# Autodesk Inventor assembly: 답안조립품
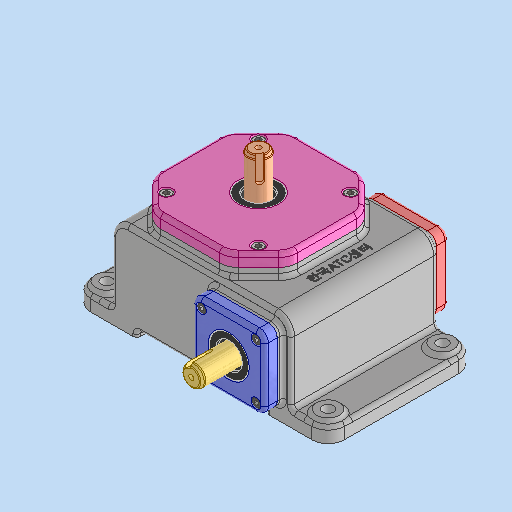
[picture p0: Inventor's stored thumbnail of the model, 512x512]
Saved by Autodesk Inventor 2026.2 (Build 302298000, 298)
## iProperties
Created: 2026-02
Part Number: 답안조립품
Document SubType Name: Assembly
Designer: PC2-07
Author: PC2-07
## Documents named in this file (15)
- C:\Users\PC2-07\Desktop\760203V1008\답안조립품.iam
- C:\Users\PC2-07\Desktop\760203V1008\본체.ipt
- C:\Users\PC2-07\Desktop\760203V1008\웜 샤프트.ipt
- C:\Users\PC2-07\Desktop\760203V1008\뒷커버.ipt
- C:\Users\PC2-07\Desktop\760203V1008\앞커버.ipt
- C:\Users\PC2-07\Desktop\760203V1008\테이퍼 롤러 베어링 30203.ipt
- C:\Users\PC2-07\Desktop\760203V1008\오일 실 17 32 8.ipt
- C:\Users\PC2-07\Desktop\760203V1008\웜 휠 커버.ipt
- C:\Users\PC2-07\Desktop\760203V1008\축.ipt
- C:\Users\PC2-07\Desktop\760203V1008\평행 키 5x5x16.ipt
- C:\Users\PC2-07\Desktop\760203V1008\웜 휠.ipt
- C:\Users\PC2-07\Desktop\760203V1008\칼라.ipt
- C:\Users\PC2-07\Desktop\760203V1008\6각 구멍붙이 볼트 M5x10.ipt
- C:\Users\PC2-07\Desktop\760203V1008\6각 구멍붙이 볼트 M4x10.ipt
- C:\Users\PC2-07\Desktop\760203V1008\6각 구멍붙이 볼트 M4x10_MIR.ipt
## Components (12 placed, 3 different names)
1. 6각 구멍붙이 볼트 M4x10_MIR:1
2. 6각 구멍붙이 볼트 M4x10_MIR:2
3. 6각 구멍붙이 볼트 M4x10_MIR:3
4. 6각 구멍붙이 볼트 M4x10_MIR:4
5. 6각 구멍붙이 볼트 M5x10:1
6. 6각 구멍붙이 볼트 M5x10:2
7. 6각 구멍붙이 볼트 M5x10:3
8. 6각 구멍붙이 볼트 M5x10:4
9. 6각 구멍붙이 볼트 M4x10:1
10. 6각 구멍붙이 볼트 M4x10:3
11. 6각 구멍붙이 볼트 M4x10:4
12. 6각 구멍붙이 볼트 M4x10:5
